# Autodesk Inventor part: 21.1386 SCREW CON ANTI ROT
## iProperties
Created: 2006-12
Part Number: 21.1386 SCREW CON ANTI ROT
Document SubType Name: Modeling
Designer: Andy Moles
Material: Aluminum-6061
Mass: 2.84475 g
Surface Area: 9.25543 cm^2
Volume: 1.04972 cm^3
Density: 2.71 g/cm^3
Author: Andy Moles
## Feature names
1. Extrusion1
2. Extrusion2
